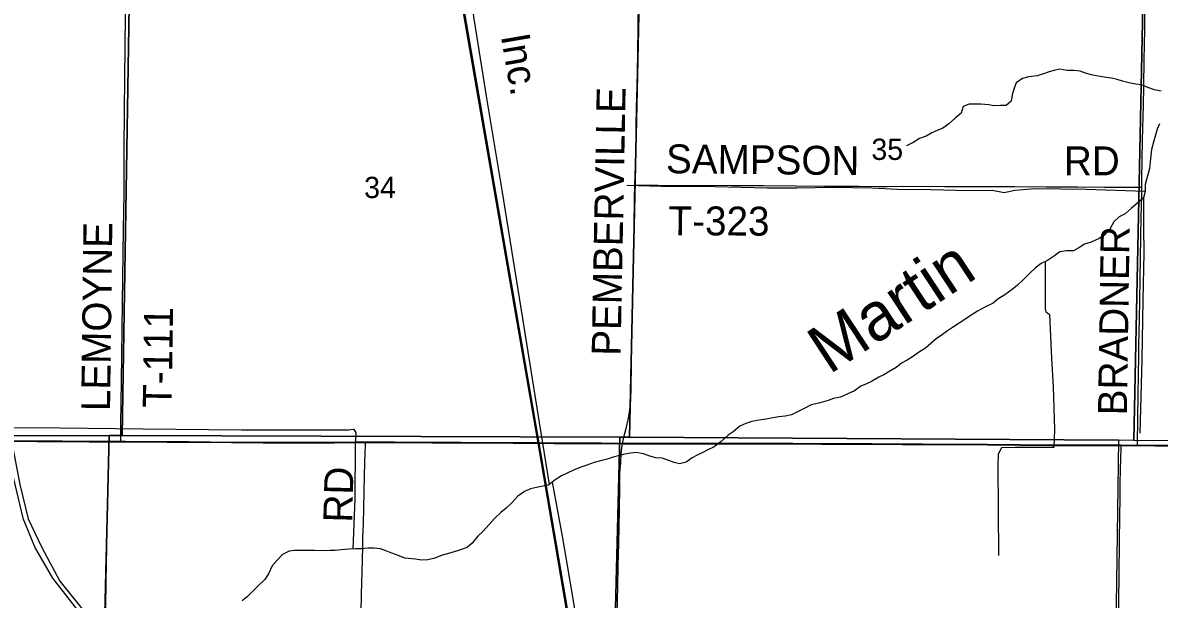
# Model space of a CAD drawing. Extents: x 0 to 34, y 0 to 22.
# Drawn here: x 3.939 to 6.172, y 18.197 to 19.331 of the extents above; entities that cross this region are included whole.
import ezdxf

# ---------------------------------------------------------------- set-up
doc = ezdxf.new("R2010")
doc.units = 0
for name, color, linetype in [('Default', 7, 'Continuous'), ('GM_X_County_Road', 7, 'Continuous'), ('GM_X_County_Road_Text', 7, 'Continuous'), ('GM_X_Minor_River', 7, 'Continuous'), ('GM_X_Minor_River_Text', 7, 'Continuous'), ('GM_X_Rail_Line', 7, 'Continuous'), ('GM_X_Rail_Line_Text', 7, 'Continuous'), ('GM_X_Section', 7, 'Continuous'), ('GM_X_Section_Text', 7, 'Continuous'), ('GM_X_Township_Road', 7, 'Continuous'), ('GM_X_Township_Road_Text', 7, 'Continuous')]:
    doc.layers.add(name, color=color, linetype=linetype)

msp = doc.modelspace()

# ---------------------------------------------------------------- linework, layer by layer
at = {"layer": 'Default'}
for points in [[(6.2138, 18.4993), (6.164, 18.4994), (6.1296, 18.4998), (6.0976, 18.5002), (6.0894, 18.5003), (6.0024, 18.5004), (5.962, 18.5004), (5.8346, 18.5015), (5.7071, 18.502), (5.6667, 18.5021), (5.6077, 18.503), (5.5517, 18.503), (5.5082, 18.5028), (5.4523, 18.5033), (5.359, 18.5035), (5.3186, 18.5033), (5.2782, 18.5032), (5.2005, 18.5032), (5.1508, 18.5035), (5.1197, 18.5036), (5.1173, 18.5036), (5.0762, 18.5039), (5.0016, 18.5043), (4.9829, 18.5044), (4.955, 18.5046), (4.9457, 18.5046), (4.9239, 18.5047), (4.9022, 18.5047), (4.8618, 18.5051), (4.7996, 18.5054), (4.7623, 18.5054), (4.7437, 18.5056), (4.6691, 18.5059), (4.6224, 18.506), (4.6122, 18.506), (4.5914, 18.506), (4.551, 18.5057), (4.4546, 18.5056), (4.4111, 18.5057), (4.3489, 18.5058), (4.265, 18.5065), (4.2215, 18.5068), (4.1407, 18.5073), (4.1312, 18.5073), (4.1075, 18.5074), (4.0692, 18.5076), (4.0163, 18.5078), (3.9666, 18.5081), (3.9169, 18.5083)], [(3.9169, 18.5083), (3.9666, 18.5081), (4.0163, 18.5078), (4.0692, 18.5076), (4.1075, 18.5074), (4.1312, 18.5073), (4.1407, 18.5073), (4.2215, 18.5068), (4.265, 18.5065), (4.3489, 18.5058), (4.4111, 18.5057), (4.4546, 18.5056), (4.551, 18.5057), (4.5914, 18.506), (4.6122, 18.506), (4.6224, 18.506), (4.6691, 18.5059), (4.7437, 18.5056), (4.7623, 18.5054), (4.7996, 18.5054), (4.8618, 18.5051), (4.9022, 18.5047), (4.9239, 18.5047), (4.9457, 18.5046), (4.955, 18.5046), (4.9829, 18.5044), (5.0016, 18.5043), (5.0762, 18.5039), (5.1173, 18.5036), (5.1197, 18.5036), (5.1508, 18.5035), (5.2005, 18.5032), (5.2782, 18.5032), (5.3186, 18.5033), (5.359, 18.5035), (5.4523, 18.5033), (5.5082, 18.5028), (5.5517, 18.503), (5.6077, 18.503), (5.6667, 18.5021), (5.7071, 18.502), (5.8346, 18.5015), (5.962, 18.5004), (6.0024, 18.5004), (6.0894, 18.5003), (6.0976, 18.5002), (6.1296, 18.4998), (6.164, 18.4994), (6.2138, 18.4993)]]:
    msp.add_lwpolyline(points, dxfattribs=at)
at = {"layer": 'GM_X_County_Road'}
for p, q in [((4.1077, 18.5069), (4.1315, 18.5068)), ((6.0978, 18.4997), (6.1298, 18.4993))]:
    msp.add_line(p, q, dxfattribs=at)
for points in [[(5.1419, 19.0116), (5.1428, 19.0494), (5.1441, 19.1004), (5.1444, 19.1253), (5.145, 19.1638), (5.1461, 19.2054), (5.1473, 19.2682), (5.1484, 19.3248), (5.149, 19.3671), (5.1492, 19.3882), (5.1498, 19.4392), (5.1499, 19.502), (5.15, 19.5196)], [(5.1175, 18.503), (5.1202, 18.5158), (5.1251, 18.5359), (5.1284, 18.5499), (5.1306, 18.5609), (5.132, 18.5702), (5.133, 18.5795), (5.1337, 18.5907), (5.1342, 18.61), (5.1352, 18.6609), (5.1358, 18.6951), (5.1389, 18.848), (5.1402, 18.9313), (5.1413, 18.9829), (5.1419, 19.0116)], [(3.1317, 18.5118), (3.1494, 18.5114), (3.1711, 18.5111), (3.2395, 18.5105), (3.2955, 18.5099), (3.3732, 18.5095), (3.4105, 18.5094), (3.4571, 18.5092), (3.5224, 18.5088), (3.5628, 18.5088), (3.6591, 18.5083), (3.684, 18.5083), (3.7306, 18.508), (3.7959, 18.5082), (3.9171, 18.5078), (3.9668, 18.5075), (4.0166, 18.5073), (4.0694, 18.5071), (4.1077, 18.5069)], [(4.1315, 18.5068), (4.1409, 18.5067), (4.2217, 18.5062), (4.2652, 18.5059), (4.3491, 18.5053), (4.4113, 18.5051), (4.4548, 18.505), (4.5512, 18.5051), (4.5916, 18.5054), (4.6125, 18.5055)], [(4.6125, 18.5055), (4.6227, 18.5055), (4.6693, 18.5053), (4.7439, 18.505), (4.7625, 18.5048), (4.7998, 18.5048), (4.862, 18.5045), (4.9024, 18.5042), (4.9242, 18.5041), (4.9459, 18.5041), (4.9552, 18.504), (4.9832, 18.5038), (5.0018, 18.5037), (5.0764, 18.5033), (5.1175, 18.503)], [(5.106, 18.1386), (5.1082, 18.2237), (5.109, 18.2598), (5.109, 18.2642), (5.11, 18.3079), (5.1106, 18.3392), (5.1114, 18.3734), (5.1119, 18.4185), (5.1125, 18.4449), (5.1139, 18.4664), (5.115, 18.482), (5.1163, 18.4954), (5.1175, 18.503)], [(5.1175, 18.503), (5.1199, 18.503), (5.151, 18.5029), (5.2007, 18.5026), (5.2784, 18.5026), (5.3188, 18.5027), (5.3592, 18.5029), (5.4525, 18.5027), (5.5084, 18.5022), (5.5519, 18.5024), (5.6079, 18.5024), (5.6669, 18.5016), (5.7074, 18.5015), (5.8348, 18.5009), (5.9622, 18.4999), (6.0026, 18.4999), (6.0896, 18.4998), (6.0978, 18.4997)], [(6.1298, 18.4993), (6.1642, 18.4989), (6.214, 18.4988), (6.2482, 18.4985), (6.2855, 18.4984), (6.3103, 18.4983), (6.3632, 18.4981), (6.4378, 18.4976), (6.4751, 18.4974), (6.559, 18.4971), (6.6616, 18.4969), (6.7237, 18.4963), (6.7797, 18.4959), (6.8605, 18.4956), (6.9071, 18.4953), (7.019, 18.4943), (7.0874, 18.494), (7.1216, 18.4939), (7.1311, 18.4939)]]:
    msp.add_lwpolyline(points, dxfattribs=at)
at = {"layer": 'GM_X_Minor_River'}
for points in [[(4.9742, 18.4232), (4.9512, 18.5653), (4.9187, 18.7654), (4.8806, 19.0012), (4.851, 19.1822), (4.8258, 19.338), (4.8125, 19.4279), (4.7979, 19.5125), (4.7736, 19.6766)], [(6.1765, 19.1963), (6.1633, 19.1989), (6.1497, 19.2031), (6.1374, 19.2083), (6.1264, 19.2101), (6.1159, 19.2118), (6.1001, 19.216), (6.0895, 19.2189), (6.0783, 19.2215), (6.0681, 19.2229), (6.0564, 19.2251), (6.0417, 19.2277), (6.0293, 19.231), (6.0169, 19.2355), (6.0044, 19.2369), (5.9912, 19.2369), (5.9772, 19.2391), (5.9658, 19.2367), (5.9562, 19.2339), (5.9448, 19.23), (5.9326, 19.2265), (5.9162, 19.2243), (5.9037, 19.2212), (5.8913, 19.2124), (5.8869, 19.1999), (5.8832, 19.1886), (5.8817, 19.1762), (5.8717, 19.1681), (5.8607, 19.1676), (5.8474, 19.1675), (5.8376, 19.1689), (5.8218, 19.1708), (5.81, 19.1707), (5.799, 19.1702), (5.7868, 19.1656), (5.7831, 19.1531), (5.7711, 19.1432), (5.759, 19.1317), (5.7471, 19.1236), (5.736, 19.1186), (5.7253, 19.1139), (5.7141, 19.1077), (5.7015, 19.1027), (5.6888, 19.0954), (5.6758, 19.0889)], [(6.173, 19.1319), (6.1685, 19.1214), (6.1644, 19.1075), (6.1611, 19.0958), (6.1573, 19.0814), (6.1559, 19.0697), (6.1548, 19.0572), (6.153, 19.044), (6.1509, 19.0342), (6.1475, 19.0221), (6.1446, 19.0123), (6.1447, 18.999), (6.1417, 18.9866), (6.1317, 18.9781), (6.1173, 18.9651), (6.1057, 18.9552), (6.0938, 18.949), (6.083, 18.939), (6.0754, 18.9248), (6.0645, 18.9122), (6.0542, 18.9067), (6.0384, 18.8995), (6.0255, 18.8953), (6.0143, 18.8879), (6.0036, 18.8825), (5.9903, 18.8821), (5.977, 18.8805), (5.9666, 18.8724), (5.9527, 18.8633), (5.9401, 18.8575), (5.9293, 18.8486), (5.9184, 18.8387), (5.9048, 18.8253), (5.8936, 18.815), (5.8835, 18.8065), (5.8692, 18.7955), (5.8554, 18.7874), (5.8457, 18.7793), (5.8296, 18.7717), (5.815, 18.7634), (5.7985, 18.7531), (5.7885, 18.7462), (5.7789, 18.74), (5.7662, 18.7315), (5.7562, 18.725), (5.7461, 18.7176), (5.7338, 18.7092), (5.7237, 18.7003), (5.7129, 18.6907), (5.699, 18.6823), (5.6894, 18.675), (5.6771, 18.6673), (5.666, 18.6611), (5.6551, 18.653), (5.6428, 18.6454), (5.6313, 18.6388), (5.6213, 18.6337), (5.6067, 18.6254), (5.5972, 18.6207), (5.5861, 18.616), (5.5733, 18.6072), (5.5603, 18.6011), (5.5462, 18.5949), (5.5321, 18.5922), (5.5214, 18.5883), (5.5031, 18.5831), (5.4882, 18.5793), (5.4748, 18.572), (5.4629, 18.5666), (5.4499, 18.5597), (5.4373, 18.5574), (5.4248, 18.5558), (5.4099, 18.5531), (5.4, 18.5511), (5.3863, 18.5491), (5.3719, 18.5468), (5.3597, 18.5429), (5.3482, 18.5379), (5.3347, 18.5265), (5.325, 18.5199), (5.3111, 18.5077), (5.2976, 18.497), (5.2841, 18.4901), (5.2738, 18.4854), (5.2642, 18.4803), (5.2546, 18.4756), (5.2423, 18.4668), (5.2293, 18.4637), (5.2192, 18.4659), (5.2087, 18.4703), (5.1952, 18.4748), (5.1827, 18.4755), (5.1714, 18.4788), (5.159, 18.4829), (5.1435, 18.4855), (5.1291, 18.4836), (5.1188, 18.4816), (5.1089, 18.4796), (5.0994, 18.4764)], [(6.1447, 18.999), (6.0289, 19.003), (5.9282, 19.0039), (5.8883, 19.0007), (5.8678, 18.9962), (5.844, 19.0006), (5.7993, 19.0002), (5.7229, 19.0024), (5.6581, 19.0025), (5.6075, 19.0052), (5.5321, 19.007), (5.4602, 19.0057), (5.4015, 19.0056), (5.2989, 19.0078), (5.194, 19.0088), (5.1259, 19.0104)], [(6.1417, 18.9866), (6.1418, 18.9277), (6.1421, 18.878), (6.1401, 18.7855), (6.138, 18.6683), (6.1344, 18.5238)], [(5.9482, 18.8612), (5.9479, 18.8064), (5.9481, 18.7681), (5.9494, 18.762), (5.9532, 18.76), (5.9569, 18.7569), (5.9605, 18.6714), (5.964, 18.6148), (5.9668, 18.5309), (5.9652, 18.4956), (5.8894, 18.4955), (5.8625, 18.4951), (5.8558, 18.4827), (5.8553, 18.4618), (5.8557, 18.3726), (5.8562, 18.2834)], [(4.5878, 18.2961), (4.5922, 18.3945), (4.5929, 18.5023), (4.5939, 18.5254), (4.5899, 18.5308), (4.588, 18.5309), (4.5792, 18.53), (4.3683, 18.5298), (4.1756, 18.5314), (4.0113, 18.5335), (3.845, 18.5341), (3.7318, 18.5319), (3.6185, 18.532), (3.5049, 18.5313), (3.3887, 18.5318), (3.2334, 18.5314)], [(5.0994, 18.4764), (5.0876, 18.4729), (5.0719, 18.4691), (5.0616, 18.4663), (5.0475, 18.4609), (5.0372, 18.4574), (5.0226, 18.4517), (5.0077, 18.4448), (4.9977, 18.4397), (4.9851, 18.4321), (4.9719, 18.4214), (4.9582, 18.4191), (4.9483, 18.417), (4.9369, 18.4147), (4.9246, 18.4089), (4.9115, 18.3997), (4.8999, 18.3867), (4.8886, 18.3764), (4.8786, 18.3682), (4.8661, 18.356), (4.8552, 18.3441), (4.8428, 18.3304), (4.8331, 18.3215), (4.8222, 18.3078), (4.8121, 18.2993), (4.7949, 18.2932), (4.7755, 18.2876), (4.7633, 18.2841), (4.7487, 18.2784), (4.735, 18.275), (4.7221, 18.2741), (4.7108, 18.2763), (4.6896, 18.2783), (4.6784, 18.2824), (4.6641, 18.2877), (4.6544, 18.2921), (4.6416, 18.2962), (4.6284, 18.298), (4.6167, 18.2979), (4.6045, 18.2963), (4.5928, 18.2962), (4.5803, 18.2958), (4.5643, 18.2947), (4.5529, 18.2934), (4.5427, 18.2929), (4.5253, 18.2926), (4.5128, 18.2932), (4.5003, 18.2932), (4.487, 18.2931), (4.4726, 18.2931), (4.4624, 18.2922), (4.4493, 18.2853), (4.4388, 18.2742), (4.4291, 18.263), (4.4215, 18.2473), (4.4144, 18.236), (4.4016, 18.2238), (4.3907, 18.2131), (4.3795, 18.2024), (4.3698, 18.1942)], [(4.9794, 18.4275), (4.999, 18.3217), (5.0188, 18.2062), (5.0402, 18.074)]]:
    msp.add_lwpolyline(points, dxfattribs=at)
at = {"layer": 'GM_X_Rail_Line'}
for points in [[(3.4414, 20.9), (3.5016, 20.5918), (3.7507, 19.321), (3.8733, 18.7042), (3.9207, 18.4339), (3.9385, 18.3568), (3.9629, 18.2975), (3.9974, 18.239), (4.1223, 18.078), (4.3281, 17.8226), (4.3689, 17.7633), (4.4066, 17.7097), (4.4454, 17.6387), (4.4793, 17.5709), (4.5132, 17.4611), (4.5342, 17.361), (4.5504, 17.2625), (4.562, 17.1188)], [(3.6732, 20.9), (3.6471, 20.09), (3.6471, 19.9081), (3.752, 19.3659), (3.9326, 18.4227), (3.949, 18.3555), (3.9754, 18.3001), (4.0116, 18.2329), (4.0712, 18.1586), (4.3307, 17.8397), (4.4282, 17.7343), (4.663, 17.5576), (4.8455, 17.4299), (4.9093, 17.3662)], [(5.1845, 16.9583), (5.1759, 17.0275), (5.1512, 17.2319), (5.1278, 17.4186), (5.1173, 17.5021), (5.1014, 17.6375), (5.0581, 17.8798), (4.9514, 18.5044), (4.7757, 19.5202), (4.6462, 20.2762), (4.5385, 20.9)], [(5.533, 14.1), (5.4414, 14.8452), (5.2368, 16.5291), (5.1973, 16.873), (5.1794, 17.0253), (5.1537, 17.2322), (5.1303, 17.4189), (5.1198, 17.5024), (5.1038, 17.6379), (5.0605, 17.8802), (4.9539, 18.5048), (4.7781, 19.5207), (4.6486, 20.2766), (4.541, 20.9)]]:
    msp.add_lwpolyline(points, dxfattribs=at)
at = {"layer": 'GM_X_Section'}
for points in [[(4.1507, 19.5243), (4.1339, 18.5191), (4.1085, 18.519), (3.1307, 18.5181), (3.1487, 19.529)], [(5.1538, 19.525), (5.1313, 18.516), (5.1123, 18.5161), (4.1339, 18.5191), (4.1507, 19.5243)], [(6.1433, 19.5215), (6.1226, 18.5095), (6.0923, 18.5098), (5.1313, 18.516), (5.1538, 19.525)], [(7.146, 19.507), (7.145, 19.4532), (7.1287, 18.4994), (6.1226, 18.5095), (6.1433, 19.5215)], [(4.1339, 18.5191), (5.1123, 18.5161), (5.0874, 17.5326), (4.6502, 17.5462), (4.0852, 17.5486), (4.1085, 18.519)], [(3.1307, 18.5181), (4.1085, 18.519), (4.0852, 17.5486), (3.0931, 17.5206), (3.1239, 18.5181)], [(5.1313, 18.516), (6.0923, 18.5098), (6.0785, 17.5378), (5.0874, 17.5326), (5.1123, 18.5161)]]:
    msp.add_lwpolyline(points, close=True, dxfattribs=at)
at = {"layer": 'GM_X_Township_Road'}
for p, q in [((4.1077, 18.5069), (4.1315, 18.5068)), ((6.0978, 18.4997), (6.1298, 18.4993))]:
    msp.add_line(p, q, dxfattribs=at)
for points in [[(6.1382, 19.0071), (6.1384, 19.024), (6.139, 19.0597), (6.1398, 19.1001), (6.1412, 19.1686), (6.1423, 19.2043), (6.143, 19.2587), (6.1435, 19.2851), (6.1437, 19.296), (6.1438, 19.3085), (6.1441, 19.3364), (6.1443, 19.3504), (6.1445, 19.366), (6.1451, 19.3971), (6.1457, 19.4282), (6.1462, 19.4546), (6.1471, 19.5074), (6.1472, 19.5128)], [(4.1315, 18.5068), (4.1315, 18.5145), (4.1316, 18.5424), (4.1327, 18.6258), (4.1335, 18.6762), (4.1343, 18.7271), (4.1348, 18.78), (4.1369, 18.9248), (4.1377, 18.9938), (4.1378, 19.0361), (4.138, 19.0716), (4.1381, 19.0927), (4.1382, 19.1107), (4.1384, 19.1263), (4.1384, 19.1387), (4.1384, 19.153), (4.1386, 19.1785), (4.139, 19.2009), (4.1392, 19.215), (4.1392, 19.2326), (4.1396, 19.2701), (4.1398, 19.2884), (4.14, 19.3052), (4.1403, 19.323), (4.141, 19.3791)], [(5.1419, 19.0116), (5.1474, 19.0116), (5.1866, 19.0114), (5.332, 19.0105), (5.3681, 19.0105), (5.3948, 19.0105), (5.4576, 19.0098), (5.5148, 19.0095), (5.549, 19.0093), (5.5819, 19.0091), (5.6217, 19.0089), (5.6378, 19.0089)], [(5.6378, 19.0089), (5.6671, 19.009), (5.751, 19.0088), (5.8393, 19.0086), (5.8884, 19.0085), (5.9499, 19.0081), (6.0127, 19.0078), (6.0649, 19.0075), (6.132, 19.0071), (6.1382, 19.0071)], [(6.1298, 18.4993), (6.1299, 18.5062), (6.1302, 18.5497), (6.1311, 18.6026), (6.1316, 18.6368), (6.1322, 18.6772), (6.1326, 18.6959), (6.1335, 18.7488), (6.1341, 18.7845), (6.1355, 18.8685), (6.1371, 18.9493), (6.1379, 18.9913), (6.1382, 19.0071)], [(4.0873, 17.5417), (4.0874, 17.5475), (4.0882, 17.5823), (4.0895, 17.6283), (4.0906, 17.6818), (4.0913, 17.7159), (4.0923, 17.7632), (4.0929, 17.8092), (4.0936, 17.8397), (4.0943, 17.8651), (4.0955, 17.9223), (4.0963, 17.9577), (4.0984, 18.0566), (4.0991, 18.0858), (4.1003, 18.1212), (4.1016, 18.1809), (4.1026, 18.2331), (4.1036, 18.299), (4.1053, 18.3804), (4.1059, 18.4096), (4.1071, 18.4618), (4.1076, 18.4966), (4.1077, 18.5069)], [(4.5927, 17.6676), (4.5929, 17.6811), (4.5934, 17.7076), (4.5942, 17.7324), (4.5956, 17.793), (4.5967, 17.8443), (4.5975, 17.8785), (4.5988, 17.9376), (4.5995, 17.9671), (4.6001, 18.006), (4.6017, 18.0791), (4.6028, 18.1319), (4.6037, 18.1723), (4.6046, 18.2065), (4.6063, 18.2749), (4.6068, 18.3013), (4.6073, 18.32), (4.6082, 18.3448), (4.6095, 18.4086), (4.6103, 18.4412), (4.6118, 18.4878), (4.6121, 18.4972), (4.6125, 18.5055)], [(6.0907, 17.9225), (6.0911, 17.9364), (6.0911, 17.9581), (6.0911, 17.9908), (6.0914, 18.0452), (6.092, 18.1011), (6.0926, 18.154), (6.0935, 18.241), (6.0943, 18.3141), (6.0954, 18.3996), (6.0959, 18.426), (6.0963, 18.4508), (6.0968, 18.4757), (6.0976, 18.4944), (6.0978, 18.4997)]]:
    msp.add_lwpolyline(points, dxfattribs=at)

# ---------------------------------------------------------------- texts
at = {"layer": 'GM_X_County_Road_Text'}
msp.add_text('PEMBERVILLE', height=0.056818, rotation=88.9085, dxfattribs=at).set_placement((5.1136, 18.6755))
at = {"layer": 'GM_X_Minor_River_Text'}
msp.add_text('Martin', height=0.09475, rotation=33.3118, dxfattribs=at).set_placement((5.5237, 18.638))
at = {"layer": 'GM_X_Rail_Line_Text'}
msp.add_text('Inc.', height=0.05663, rotation=279.7937, dxfattribs=at).set_placement((4.8781, 19.3045))
at = {"layer": 'GM_X_Section_Text'}
for s, p in [('35', (5.6067, 19.0609)), ('34', (4.6097, 18.9859))]:
    msp.add_text(s, height=0.04186, rotation=0, dxfattribs=at).set_placement(p)
at = {"layer": 'GM_X_Township_Road_Text'}
for s, rotation, p in [('SAMPSON', 359.4194, (5.2028, 19.0348)), ('RD', 0, (5.9851, 19.0307)), ('T-323', 359.7178, (5.2078, 18.913)), ('LEMOYNE', 89.2965, (4.1102, 18.5668)), ('BRADNER', 89.1385, (6.1088, 18.5586)), ('T-111', 89.1587, (4.2312, 18.5732)), ('RD', 88.5174, (4.5861, 18.3476))]:
    msp.add_text(s, height=0.05682, rotation=rotation, dxfattribs=at).set_placement(p)

doc.saveas('drawing.dxf')
